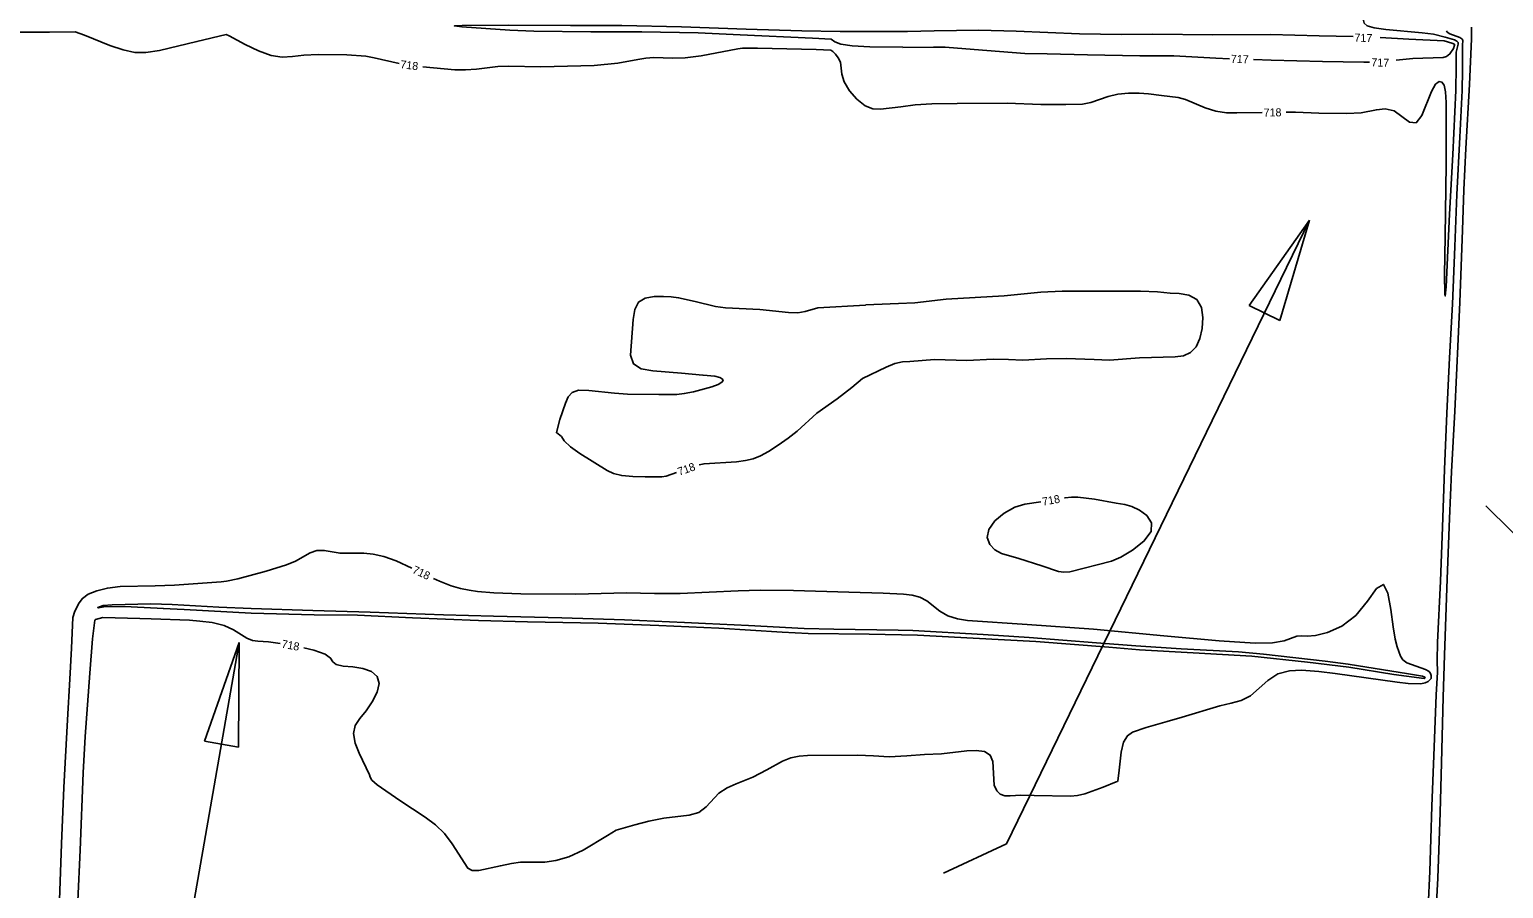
# Model space of a CAD drawing. Extents: x -310467766 to 17062430, y -322263100 to 8322522.
# Drawn here: x 1394957 to 1395694, y 572146 to 572575 of the extents above; entities that cross this region are included whole.
import ezdxf

# ---------------------------------------------------------------- set-up
doc = ezdxf.new("R2010")
doc.units = 0
for name, color, linetype in [('DT_X_Contour_Minor', 7, 'Continuous'), ('Level 19', 7, 'Continuous'), ('Level 40', 7, 'Continuous')]:
    doc.layers.add(name, color=color, linetype=linetype)

msp = doc.modelspace()

# ---------------------------------------------------------------- linework, layer by layer
at = {"layer": 'DT_X_Contour_Minor'}
for points in [[(1395609.37, 572589.53), (1395616.34, 572589), (1395619.58, 572587.93), (1395621.67, 572585.75), (1395622.85, 572582.96), (1395624.08, 572578.35), (1395625.55, 572577), (1395628.97, 572576), (1395634.9, 572575.13), (1395652.96, 572573.5), (1395658.58, 572572.82), (1395664.55, 572571.4), (1395669.17, 572569.99), (1395670.37, 572569.38)], [(1395393.8, 572574.21), (1395362.17, 572574.14), (1395343.03, 572574.51), (1395315.06, 572575.29), (1395282.77, 572576.55), (1395252.93, 572577.15), (1395227.41, 572577.18), (1395196.29, 572577.27), (1395173.12, 572577.21), (1395169.35, 572576.95), (1395172.99, 572576.45), (1395196.98, 572574.82), (1395208.99, 572574.39), (1395237.42, 572574.02), (1395263.05, 572573.99), (1395291.1, 572573.44), (1395312.14, 572572.47), (1395348.26, 572570.8), (1395357.64, 572570.32), (1395359.48, 572568.92), (1395362.36, 572567.86), (1395368.03, 572566.96), (1395376.99, 572566.46), (1395393.5, 572566.27)], [(1394950.07, 572573.83), (1394966.96, 572573.88), (1394979.81, 572574.05), (1394984.5, 572572.25), (1394997.04, 572567.23), (1395003.82, 572564.93), (1395009.5, 572563.71), (1395015.07, 572563.65), (1395021.97, 572564.71), (1395040.64, 572569.08), (1395055.3, 572572.68), (1395056.69, 572572.01), (1395064.81, 572567.67), (1395071.31, 572564.54), (1395077.78, 572562.17), (1395083.26, 572561.36), (1395088.37, 572561.65), (1395094.11, 572562.27), (1395101.14, 572562.58), (1395115.46, 572562.41), (1395125.08, 572561.75), (1395129.16, 572561.04)], [(1395618.53, 572571.58), (1395601.56, 572572), (1395577.13, 572572.58), (1395548.23, 572572.51), (1395518.35, 572572.76), (1395502.67, 572572.58), (1395481.79, 572573.05), (1395450.13, 572574.35), (1395431.37, 572574.76), (1395409.04, 572574.47), (1395395.69, 572574.19), (1395393.8, 572574.21)], [(1395670.37, 572569.38), (1395670.91, 572568.68), (1395670.91, 572567.79), (1395670.02, 572563.86), (1395670.01, 572556.67), (1395669.75, 572544.69), (1395668.24, 572512.73), (1395666.73, 572482.85), (1395664.91, 572446.53), (1395664.51, 572441.98), (1395664.35, 572443.08), (1395664.21, 572452.4), (1395664.54, 572471.82), (1395664.92, 572507.62), (1395664.99, 572538.7), (1395664.62, 572544.02), (1395663.94, 572547.27), (1395662.89, 572548.89), (1395661.44, 572549.17), (1395659.65, 572547.75), (1395657.6, 572544.12), (1395652.82, 572532.21), (1395649.96, 572528.5), (1395646.68, 572528.83), (1395638.92, 572534.43), (1395634.52, 572535.43), (1395630.12, 572535.01), (1395622.54, 572533.53), (1395615.4, 572533.19), (1395601.28, 572533.32), (1395589.74, 572533.84), (1395585, 572533.78)], [(1395640.06, 572559.78), (1395648.34, 572560.59), (1395663.53, 572561.14), (1395665.1, 572561.59), (1395666.88, 572562.94), (1395668.58, 572565.66), (1395669.23, 572567.27), (1395669.11, 572567.76), (1395667.86, 572568.36), (1395663.94, 572569.45), (1395646.33, 572570.26), (1395631.92, 572571.11)], [(1395665.08, 572574.47), (1395665.48, 572573.82), (1395666.88, 572572.98), (1395671.76, 572571.09), (1395672.81, 572570.47), (1395673.28, 572569.86), (1395673.22, 572567.08), (1395673.21, 572554.88), (1395672.91, 572544.66), (1395671.76, 572521.27), (1395670.35, 572492.67), (1395669.24, 572466.68), (1395668.08, 572437.96), (1395666.71, 572411.02), (1395665.34, 572383.51), (1395664.17, 572355.36), (1395663.16, 572326.51), (1395662.08, 572299.41), (1395660.73, 572268.84), (1395660.52, 572259.88), (1395660.74, 572254.06), (1395659.96, 572242.71), (1395658.8, 572212.27), (1395657.82, 572187.13), (1395656.85, 572154.37), (1395656.05, 572136.67)], [(1395677.62, 572576.35), (1395677.65, 572570.5), (1395676.67, 572547.73), (1395674.9, 572515.71), (1395673.86, 572495.02), (1395673.15, 572474.9), (1395671.84, 572438.87), (1395670.99, 572420.38), (1395669.32, 572384.41), (1395667.72, 572354.11), (1395666.68, 572330.84), (1395665.51, 572300.58), (1395664.16, 572262.46), (1395663.54, 572241.49), (1395662.68, 572208.75), (1395661.91, 572183.88), (1395660.78, 572151.09), (1395659.71, 572129.51)], [(1395153.51, 572556.5), (1395169.44, 572555.02), (1395174.92, 572554.92), (1395180.3, 572555.36), (1395190.96, 572556.63), (1395196.35, 572556.77), (1395212.57, 572556.5), (1395239.19, 572557.15), (1395250.96, 572558.35), (1395260.96, 572560.11), (1395265.04, 572560.86), (1395268.98, 572561.22), (1395278.23, 572560.84), (1395284.65, 572561.05), (1395292.61, 572562.04), (1395310.96, 572565.46), (1395313.26, 572565.82), (1395320.73, 572565.75), (1395350.12, 572565.17), (1395357.46, 572564.74), (1395358.46, 572564.08), (1395359.73, 572562.85), (1395361.17, 572561.06), (1395362.23, 572558.78), (1395362.99, 572552.8), (1395364.19, 572548.94), (1395366.83, 572544.52), (1395370.51, 572540.27), (1395374.55, 572537.07), (1395378.44, 572535.53), (1395382.27, 572535.3), (1395392.37, 572536.54)], [(1395393.5, 572566.23), (1395408.77, 572566.4), (1395414.65, 572566.25), (1395429.08, 572565.1), (1395454.45, 572563.08), (1395465.5, 572562.92), (1395485.67, 572562.5), (1395511.94, 572561.99), (1395528.94, 572562), (1395549.93, 572560.78), (1395556.64, 572560.55)], [(1395129.16, 572561.04), (1395141.62, 572558.12)], [(1395568.63, 572560.14), (1395577.47, 572559.83), (1395603.12, 572559.17), (1395623.86, 572558.76), (1395626.72, 572558.87)], [(1395573, 572533.63), (1395560.31, 572533.47), (1395555.26, 572533.54), (1395549.9, 572534.3), (1395544.48, 572536.03), (1395534.77, 572540.09), (1395531.01, 572541.16), (1395522.67, 572542.13), (1395516.17, 572542.96), (1395511.49, 572543.32), (1395506.2, 572543.38), (1395500.91, 572542.85), (1395496.08, 572541.61), (1395487.44, 572538.68), (1395483.28, 572537.91), (1395474.97, 572537.59), (1395462.44, 572537.74), (1395445.58, 572538.33), (1395420.55, 572538.17), (1395407.93, 572538.01), (1395399.58, 572537.48), (1395392.37, 572536.54)], [(1395374.9, 572437.54), (1395378.93, 572437.75), (1395391.23, 572438.21), (1395399.41, 572438.58), (1395415.08, 572440.48), (1395444.15, 572442.14), (1395462.37, 572443.85), (1395473.07, 572444.34), (1395482.83, 572444.46), (1395512.3, 572444.44), (1395520.71, 572444.03), (1395527.12, 572443.46), (1395531.6, 572443.2), (1395536.38, 572442.36), (1395540.35, 572440.21), (1395542.63, 572436.3), (1395543.39, 572431.21), (1395543.03, 572425.78), (1395541.89, 572420.79), (1395539.99, 572416.65), (1395537.24, 572413.68), (1395533.66, 572412.09), (1395529.48, 572411.5), (1395511.77, 572411.14), (1395496.66, 572409.99), (1395489.08, 572410.24), (1395474.99, 572410.83), (1395465.31, 572410.5), (1395453.36, 572409.97), (1395446.29, 572410.23), (1395438.53, 572410.44), (1395425.5, 572409.67), (1395409.19, 572410.18), (1395396.95, 572409.32), (1395393.29, 572409.03), (1395389.38, 572408.18), (1395385.02, 572406.5), (1395373.28, 572400.75), (1395367.92, 572396.2), (1395360.56, 572390.54), (1395350.4, 572383.47), (1395340.63, 572374.5), (1395336.05, 572370.91), (1395331.07, 572367.39), (1395326.35, 572364.36), (1395322.32, 572362.13), (1395318.65, 572360.64), (1395314.77, 572359.71), (1395310.31, 572359.19), (1395294.12, 572358.16), (1395291.69, 572357.58)], [(1395374.75, 572437.48), (1395350.96, 572436.08), (1395344.59, 572434.21), (1395340.89, 572433.64), (1395336.27, 572433.74), (1395321.9, 572435.21), (1395304.81, 572436.03), (1395299.79, 572436.76), (1395289.7, 572439.16), (1395281.33, 572441.12), (1395277.69, 572441.59), (1395273.73, 572441.81), (1395269.18, 572441.75), (1395264.71, 572440.98), (1395261.25, 572438.95), (1395259.43, 572435.28), (1395258.72, 572430.27), (1395257.37, 572412.45), (1395258.83, 572408.06), (1395262.71, 572405.62), (1395268.54, 572404.57), (1395282.77, 572403.47), (1395293.52, 572402.37)], [(1395271.42, 572392.81), (1395280.47, 572392.84), (1395284.21, 572393.25), (1395288.79, 572394.13), (1395298, 572396.61), (1395301.15, 572397.81), (1395303.01, 572398.88), (1395303.62, 572399.83), (1395303.11, 572400.64), (1395301.92, 572401.28), (1395299.46, 572401.89), (1395293.67, 572402.43)], [(1395271.42, 572392.81), (1395255.74, 572392.99), (1395249.38, 572393.4), (1395236.43, 572394.83), (1395231.38, 572394.85), (1395228.11, 572393.75), (1395226.14, 572391.56), (1395224.75, 572388.39), (1395222.01, 572380.31), (1395220.32, 572373.76), (1395222.86, 572371.82)], [(1395280.31, 572353.76), (1395275.09, 572351.9), (1395272.97, 572351.61), (1395264.66, 572351.59), (1395258.55, 572351.77), (1395252.94, 572352.27), (1395248.85, 572353.24), (1395245.58, 572354.78), (1395232.02, 572363.24), (1395227.39, 572366.57), (1395224.15, 572369.64), (1395222.86, 572371.82)], [(1395462.35, 572339.06), (1395454.34, 572338.01), (1395449.34, 572336.39), (1395444.08, 572333.45), (1395439.4, 572329.58), (1395436.34, 572325.37), (1395435.64, 572321.36), (1395436.9, 572317.86), (1395439.43, 572315.14), (1395442.68, 572313.35), (1395451.49, 572310.78), (1395462.88, 572307.18), (1395471.24, 572304.37), (1395473.96, 572303.91), (1395476.95, 572304.2), (1395497.77, 572309.49), (1395502.43, 572311.44), (1395508.28, 572314.93), (1395513.91, 572319.45), (1395517.48, 572324.23), (1395517.69, 572328.6), (1395515.31, 572332.25), (1395511.64, 572335.02), (1395507.83, 572336.78), (1395504.45, 572337.74), (1395500, 572338.53), (1395489.17, 572340.51), (1395480.92, 572341.53), (1395477.66, 572341.54), (1395474.49, 572341.2), (1395474.17, 572341.14)], [(1395148.07, 572305.9), (1395140.24, 572309.57), (1395133.97, 572311.78), (1395128.62, 572313.02), (1395123.98, 572313.5), (1395112.13, 572313.45), (1395104.29, 572314.81), (1395100.59, 572314.8), (1395097.17, 572313.62), (1395089.92, 572309.49), (1395085.4, 572307.61), (1395075.15, 572304.51), (1395061.07, 572300.6), (1395055.45, 572299.51)], [(1395055.34, 572299.46), (1395052.78, 572299.15), (1395029.47, 572297.43), (1395019.79, 572297.15), (1395002.25, 572296.86), (1394995.9, 572296), (1394990.64, 572294.71), (1394986.19, 572292.99), (1394983.36, 572290.85), (1394981.68, 572288.73), (1394979.63, 572284.5), (1394978.58, 572281.32), (1394977.87, 572266.07)], [(1395645.99, 572248.35), (1395652.28, 572248.23), (1395654.53, 572248.68), (1395656.04, 572249.37), (1395657.43, 572250.85), (1395657.48, 572252.35), (1395657.22, 572253.29), (1395656.44, 572254.33), (1395654.69, 572255.39), (1395645.31, 572258.7), (1395643.33, 572260.18), (1395642.15, 572261.95), (1395640.47, 572266.62), (1395639.52, 572270.51), (1395638.51, 572276.67), (1395637.4, 572285.3), (1395635.88, 572293.57), (1395633.59, 572297.88), (1395630.22, 572295.79), (1395625.65, 572289.49), (1395619.81, 572282.34), (1395612.84, 572277.06), (1395605.73, 572273.87), (1395599.65, 572272.35), (1395595.46, 572272.03), (1395592.65, 572272.18), (1395590.39, 572272.02), (1395584.05, 572269.64), (1395578.12, 572268.64), (1395569.61, 572268.53), (1395551.61, 572269.71), (1395523.94, 572272.13), (1395488.73, 572275.46), (1395455.55, 572277.86), (1395425.74, 572279.9), (1395420.72, 572280.63), (1395415.92, 572282.1), (1395411.96, 572284.46), (1395405.39, 572289.72), (1395401.94, 572291.44), (1395398.09, 572292.47), (1395393.77, 572293.03), (1395383.66, 572293.44), (1395366.44, 572293.92), (1395338.74, 572294.82), (1395322.15, 572295.03), (1395311.07, 572294.71), (1395282.21, 572293.26), (1395269.36, 572293.38), (1395255.37, 572293.58), (1395229.97, 572293), (1395202.45, 572293.2), (1395188.93, 572293.7), (1395180.91, 572294.38), (1395176.72, 572294.94), (1395172.42, 572295.79), (1395167.64, 572297.18), (1395161.9, 572299.43), (1395158.94, 572300.82)], [(1395028.26, 572287.79), (1395017.55, 572288.23), (1394998.21, 572287.65), (1394993.77, 572287.29), (1394991.07, 572286.25), (1394991.42, 572286.22), (1394994.12, 572286.74), (1394997.34, 572286.88), (1395007.79, 572286.61), (1395023.87, 572285.9)], [(1395023.74, 572285.84), (1395034.29, 572285.33), (1395067.73, 572283.5), (1395099.23, 572282.66), (1395120.88, 572282.42), (1395148.33, 572281.21), (1395181.35, 572279.91), (1395205.83, 572279.24), (1395241.2, 572278.46), (1395271.56, 572277.3), (1395301.52, 572276.06), (1395333.07, 572273.99), (1395346.12, 572273.32), (1395376.68, 572272.97), (1395400.68, 572272.54), (1395428.62, 572271.02), (1395459.86, 572269.33), (1395496.31, 572266.48), (1395511.71, 572265.1), (1395538.59, 572263.74), (1395567.94, 572262), (1395595.61, 572258.94), (1395616.3, 572256.43), (1395638.86, 572252.91), (1395654.06, 572250.78), (1395654.48, 572251.18), (1395654.28, 572251.59), (1395653.08, 572251.98), (1395646.24, 572253.16), (1395616.04, 572257.93), (1395604.44, 572259.44), (1395573.64, 572262.95), (1395561.28, 572264.13), (1395532.46, 572265.73), (1395509.91, 572267.12), (1395490.29, 572268.71), (1395456.61, 572271.38), (1395433.58, 572272.8), (1395398.45, 572274.79), (1395391.12, 572275.03), (1395359, 572275.48), (1395344.07, 572275.89), (1395316.37, 572277.29), (1395294.73, 572278.39), (1395284.24, 572278.79), (1395254.34, 572280.12), (1395223.01, 572281.15), (1395188.87, 572281.97), (1395163.85, 572282.73), (1395127.12, 572283.96), (1395098.53, 572284.87), (1395067.78, 572285.89), (1395051.61, 572286.55), (1395028.26, 572287.79)], [(1394988.41, 572270.62), (1394989.56, 572280.01), (1394989.97, 572280.25), (1394993.59, 572281.25), (1395012.01, 572280.79)], [(1395012.02, 572280.79), (1395017.68, 572280.65), (1395036.83, 572279.96), (1395042, 572279.56), (1395048.21, 572278.76), (1395054.2, 572277.35), (1395058.95, 572275.23), (1395065.64, 572270.95), (1395068.37, 572269.87), (1395070.99, 572269.44), (1395076.36, 572269.11), (1395082.27, 572268.29)], [(1394981.11, 572139.73), (1394982.26, 572165.04), (1394983.81, 572203.76), (1394984.78, 572221.88), (1394987.03, 572253.49), (1394988.41, 572270.62)], [(1394977.87, 572266.07), (1394977.15, 572250.56), (1394975.88, 572230.15), (1394974.1, 572196.37), (1394972.94, 572168.29), (1394971.95, 572140.12)], [(1395094.07, 572266.13), (1395099.06, 572264.98), (1395104.65, 572263.06), (1395107.39, 572261.03), (1395108.59, 572259.19), (1395110.24, 572257.82), (1395113.77, 572257.09), (1395118.6, 572256.61), (1395123.62, 572255.83), (1395127.83, 572254.3), (1395130.68, 572251.85), (1395131.73, 572248.4), (1395130.74, 572244.01), (1395128.28, 572239.22), (1395125.13, 572234.7), (1395122.05, 572230.89), (1395119.73, 572227.34), (1395118.8, 572223.38), (1395119.68, 572218.6), (1395121.67, 572213.59), (1395126.8, 572202.66), (1395127.12, 572201.54), (1395128.11, 572200.11), (1395130.75, 572197.79), (1395142.03, 572189.87), (1395154.69, 572181.56), (1395159.9, 572177.74), (1395164.4, 572173.42), (1395168.24, 572168.31), (1395175.95, 572156.02), (1395178.14, 572154.83), (1395181.45, 572154.9), (1395192.28, 572157.29), (1395197.85, 572158.47), (1395202.32, 572159.01), (1395214.57, 572159.06), (1395220.05, 572159.82), (1395226.45, 572161.77), (1395233.6, 572165.13), (1395245.82, 572172.36), (1395250.17, 572175.05), (1395259.55, 572177.79), (1395266.51, 572179.58), (1395273.92, 572181.03), (1395286.69, 572182.48), (1395291.49, 572183.91), (1395295.12, 572186.66), (1395301.51, 572193.57), (1395305.61, 572196.23), (1395310.15, 572198.26), (1395318.44, 572201.57), (1395325.52, 572205.22), (1395333.37, 572209.52), (1395337.53, 572211.18), (1395341.69, 572212.09), (1395345.85, 572212.42), (1395370.76, 572212.61), (1395378.69, 572212.22), (1395386.64, 572211.77), (1395395.37, 572212.27), (1395404.24, 572212.82), (1395412.75, 572213.25), (1395425.49, 572214.71), (1395430.06, 572214.87), (1395434.19, 572214.32), (1395437.12, 572212.56), (1395438.37, 572209.34), (1395439.12, 572197.5), (1395440.34, 572194.76), (1395442.15, 572192.99), (1395444.46, 572192.23), (1395447.09, 572192.15), (1395452.49, 572192.48), (1395459.14, 572192.42), (1395477.21, 572192.01), (1395480.65, 572192.37), (1395484.41, 572193.27), (1395493.5, 572196.58), (1395500, 572199.26), (1395500.68, 572199.38), (1395500.86, 572199.68), (1395501.32, 572203.6), (1395502.48, 572214.04), (1395503.74, 572219.05), (1395505.65, 572222.26), (1395508.22, 572224.06), (1395515.02, 572226.4), (1395525.53, 572229.44), (1395533.1, 572231.53), (1395551.84, 572237.11), (1395557.58, 572238.44), (1395562.6, 572239.87), (1395567.12, 572242.18), (1395575.83, 572249.85), (1395580.88, 572253.12), (1395586.76, 572254.71), (1395592.71, 572255.01), (1395601.34, 572254.41), (1395609.58, 572253.36), (1395640.55, 572248.94), (1395645.99, 572248.35)]]:
    msp.add_lwpolyline(points, dxfattribs=at)
at = {"layer": 'Level 40'}
for p, q in [((1395445.23, 572168.23), (1395596.75, 572479.84)), ((1395566.46, 572437.22), (1395596.75, 572479.84)), ((1395596.75, 572479.84), (1395581.91, 572429.71)), ((1395581.91, 572429.71), (1395566.46, 572437.22)), ((1395684.84, 572337.08), (1396318.06, 571710.25)), ((1395003.67, 571936.21), (1395061.74, 572268.89)), ((1395044.4, 572219.56), (1395061.74, 572268.89)), ((1395061.74, 572268.89), (1395061.32, 572216.6)), ((1395061.32, 572216.6), (1395044.4, 572219.56)), ((1395413.69, 572153.51), (1395445.23, 572168.23))]:
    msp.add_line(p, q, dxfattribs=at)

# ---------------------------------------------------------------- texts
at = {"layer": 'Level 19'}
for s, rotation, p in [('717', 358.04133, (1395619.08, 572569.14)), ('717', 358.04133, (1395557.31, 572558.52)), ('718', 353.26859, (1395142.11, 572555.83)), ('717', 358.04133, (1395627.51, 572556.79)), ('718', 0.70474, (1395573.78, 572531.64)), ('718', 19.22846, (1395281.68, 572352.12)), ('718', 10.23302, (1395463.46, 572337.18)), ('718', 334.92248, (1395147.91, 572303.77)), ('718', 349.53863, (1395082.67, 572266.3))]:
    msp.add_text(s, height=4, rotation=rotation, dxfattribs=at).set_placement(p)

doc.saveas('drawing.dxf')
